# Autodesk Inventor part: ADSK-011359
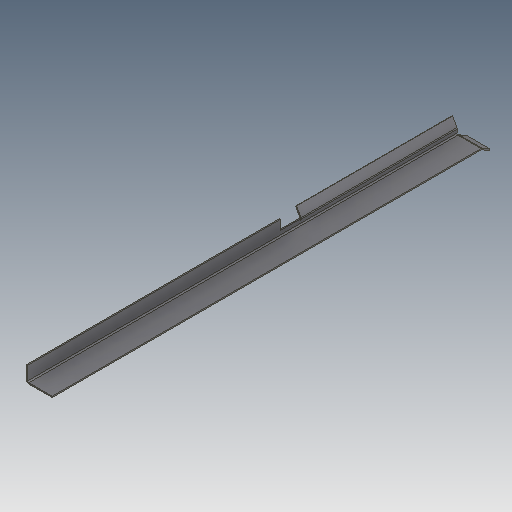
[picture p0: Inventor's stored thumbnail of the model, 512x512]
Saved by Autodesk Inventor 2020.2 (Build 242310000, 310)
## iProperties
Created: 1999-12
Part Number: ADSK-011359
Material: 1.0312 DC05
Document SubType Name: Tôlerie
Designer: sspink
Density: 1 g/cm^3
Sheet Metal Rule: Stahlblech 1.0312 - DC05 -   3.0 mm
Appearance: Stahl
Mass: 343.254 g
Surface Area: 2364.73 cm^2
Volume: 343.254 cm^3
Flat Pattern Width: 10.229 cm
Flat Pattern Length: 114.205 cm
Flat Pattern Area: 1168.2 cm^2
Sheet Metal Width: 102,290 mm
Sheet Metal Length: 1142,047 mm
Sheet Metal Area: 116819,823 mm^2
Control State: 0
Master: False
Checked Out: False
Shininess: 57.0
Length Units: 11269
Angle Units: 11279
Time Units: 11290
Mass Units: 11283
Length Display Precision: 3
Angle Display Precision: 2
Compacted: True
Cutlength: 3.81 X 45.03 (172 SI)
Material Desc: SHEET,S/S, 11 GA
Material_number: A084638
G_L: 102,3x1142 mm
Thickness: 3,000 mm
Dimensions: 53,1x1139,7x78,7 mm
Mass: 0,343 kg
Semi finished: Stahlblech 1.0312 - DC05 -   3.0 mm
VLT_Material: 1.0312 DC05
Density: 0.0
Volumn: 0.0
Area: 0.0
PropertySet Name: Model Information
Author: sspink
Revision Number: -
Title: ADSK-011359
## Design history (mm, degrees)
derived "ADSK-011362.ipt"
feature "Solide1::ADSK-011362.ipt" dims "d82" = 10
tag "Bezeichnung2"
node "Volumenkörper3"
node "Corps solides"
node "Corps surfaciques"
feature "Definition1"
other parameters: "Thickness" = 3 (derived), "BendRadius" = 3 (= Thickness), "BendReliefWidth" = 3 (= Thickness), "BendReliefDepth" = 1.5 (= 0.5 x Thickness), "CornerReliefSize" = 12 (= 4 x Thickness), "SeamGap" = 0.00508, "MinimumRemnant" = 6 (= 2 x Thickness), "TransitionRadius" = 3 (= BendRadius), "TailleRayonJacobi" = 3 (= BendRadius), "TailleJeu" = 3 (= Thickness), "d83" = 3 (= Thickness), "BendRadius" = 3, "BendReliefDepth" = 1.5, "BendReliefWidth" = 3, "CornerReliefSize" = 12, "MinimumRemnant" = 6, "TailleJeu" = 3, "TailleRayonJacobi" = 3, "Thickness" = 3, "TransitionRadius" = 3
